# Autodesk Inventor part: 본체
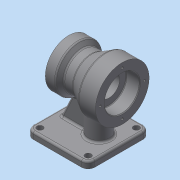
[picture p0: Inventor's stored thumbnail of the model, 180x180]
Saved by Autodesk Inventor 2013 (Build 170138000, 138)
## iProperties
Created: 2019-01
Part Number: 본체
Material: 일반
Document SubType Name: Modeling
Designer: Administrator
Density: 1 g/cm^3
Author: Administrator
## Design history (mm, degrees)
sketch "스케치1"
  geometry: L1 (46, 46)-(-46, 46); L2 (-46, 46)-(-46, -46); L3 (-46, -46)-(46, -46); L4 (46, -46)-(46, 46); L5 (46, 46)-(-46, -46); L6 (-46, 46)-(46, -46); 1 further point
  constraints: 12 end point, 2 midpoint, 2 parallel, 1 horizontal, 1 perpendicular
  dimensions: "d0" = 92 distance of L1.start L1.end; "d2" = 92 distance of L3.end L1.start
extrude "돌출1" new body sketch "스케치1" distance "d3" = 10; taper "d4" = 0 deg
sketch "스케치2"
  geometry: L1 (-77.092, 80)-(63.387, 80); L2 (-51, 80)-(-51, 120); L3 (-51, 120)-(-26, 120); L4 (-26, 120)-(-5.215, 108); L5 (-5.215, 108)-(8.126, 108); L6 (8.126, 108)-(14, 115); L7 (14, 115)-(29, 115); L8 (29, 115)-(29, 80); L9 (-46, 0)-(-46, 10) reference; 1 further point
  constraints: 16 end point, 3 perpendicular, 2 parallel, 2 point on line, 1 horizontal
  dimensions: "d5" = 80 vertical distance of point (0, 0) L1.start; "d6" = 5 distance between parallel lines of L9 L2; "d7" = 25 distance of L2.end L3.end; "d8" = 15 distance of L6.end L7.end; "d9" = 80 diameter of L3 L1; "d10" = 70 diameter of L7 L1; "d11" = 30 deg angle of L5 L4; "d12" = 50 deg angle of L5 L6; "d13" = 56 diameter of L5 L1; "d14" = 80 distance between parallel lines of L8 L2
revolve "회전1" sketch "스케치2" stored, may be unused: angle "d15" = 90 deg
sketch "스케치3"
  geometry: L1 (46, 46)-(-46, 46) reference; L2 (46, -46)-(46, 46) reference; C1 r 16 at (16, 0); 1 further point
  constraints: 1 centre point
  dimensions: "d16" = 32 diameter of C1; "d18" = 30 distance from line of C1.centre L2; "d19" = 46 distance from line of C1.centre L1
extrude "돌출2" join sketch "스케치3" stored distance "d20" = 10; taper "d21" = 0 deg
sketch "스케치4"
  geometry: L1 (0, 10)-(0, 52) reference; L2 (46, 10)-(-46, 10) reference; L3 (8.126, 52)-(14, 45) reference; L4 (0, 52)-(8.126, 52) reference; L5 (19.679, 45)-(36, 10); L6 (36, 10)-(0, 10); L7 (46, 0)-(46, 10) reference; L8 (14, 45)-(29, 45) reference; 1 further point
  constraints: 4 end point, 2 point on line, 1 collinear
  dimensions: "d22" = 25 deg angle of L7 L5; "d23" = 10 distance from line of L7 L5.end
feature "리브1" sketch "스케치4" dims "d24" = 1, "d25" = 10, "d26" = 0, "d27" = 0, "d28" = 1, "d29" = 1
sketch "스케치5"
  geometry: L1 (-51, 40)-(-51, 120) reference; L2 (-74.237, 80)-(66.433, 80); L3 (-51, 106)-(-31, 106); L4 (-31, 106)-(-31, 96); L5 (-31, 96)-(12, 96); L6 (12, 96)-(12, 100); L7 (29, 45)-(29, 115) reference; L8 (12, 100)-(29, 100); L9 (29, 100)-(29, 80); L10 (29, 80)-(-51, 80); L11 (-51, 80)-(-51, 106); 1 further point
  constraints: 18 end point, 3 parallel, 3 perpendicular, 3 point on line, 2 midpoint, 1 collinear
  dimensions: "d30" = 80 vertical distance of L2.end point (0, 0); "d31" = 20 distance of L3.start L3.end; "d32" = 17 distance of L6.end L8.end; "d33" = 52 diameter of L3 L2; "d34" = 40 diameter of L8 L2; "d35" = 32 diameter of L5 L2
revolve "회전2" sketch "스케치5" stored, may be unused: angle "d36" = 90 deg
fillet "모깎기1" dims "d37" = 10
fillet "모깎기2" dims "d38" = 3
sketch "스케치6"
  geometry: C1 r 4.5 at (-36, 36); C2 r 4.5 at (36, 36); C3 r 4.5 at (36, -36); C4 r 4.5 at (-36, -36); A1 r 7 centre (-36, 36) between (-36, 43) and (-43, 36) reference; A2 r 7 centre (-36, -36) between (-43, -36) and (-36, -43) reference; A3 r 7 centre (36, -36) between (36, -43) and (43, -36) reference; A4 r 7 centre (36, 36) between (43, 36) and (36, 43) reference; 1 further point
  constraints: 4 centre point, 4 coincident, 3 equal radius
  dimensions: "d39" = 9 diameter of C1
extrude "돌출3" cut sketch "스케치6" distance "d41" = 10; taper "d42" = 0 deg
sketch "스케치7" dims "d43" = 66
  geometry: C1 r 26 at (0, 0) reference; 2 further points
  constraints: 2 horizontal alignment, 2 other
hole "구멍1" sketch "스케치7" at (-33, 0) diameter "d45" = 3.242; stored, may be unused: countersink angle "d49" = 90 deg, drill point angle "d51" = 118 deg; dims "d46" = 9, "d47" = 4, "d48" = 2, "d50" = 11
sketch "스케치8" dims "d55" = 55
  geometry: C1 r 20 at (0, 0) reference; 2 further points
  constraints: 2 horizontal alignment, 2 other
hole "구멍2" sketch "스케치8" at (27.5, 0) diameter "d57" = 3.242; stored, may be unused: countersink angle "d61" = 90 deg, drill point angle "d63" = 118 deg; dims "d58" = 9, "d59" = 4, "d60" = 2, "d62" = 11
fillet "모깎기3" dims "d67" = 1
chamfer "모따기1" distance "d68" = 1; stored, may be unused: second distance "d69" = 2, angle "d70" = 45 deg
fillet "모깎기4" dims "d71" = 0.6
fillet "모깎기5" dims "d72" = 3
fillet "모깎기6" dims "d73" = 3
fillet "모깎기7" dims "d74" = 3
sketch "스케치9"
  geometry: L1 (72, 0)-(0, 0) reference; L2 (82, -7)-(82, 0) reference; 2 further points
  constraints: 1 other
  dimensions: "d75" = 4 distance from line of point (36, -4) L1; "d76" = 46 distance from line of point (36, -4) L2
feature "엠보싱1" sketch "스케치9" dims "d0" = 92, "d2" = 92, "d77" = 0.5, "d78" = 0
node "솔리드1"
pattern_circular "원형 패턴1" dims angle "d53" = 360 deg
pattern_circular "원형 패턴2" dims angle "d65" = 360 deg
